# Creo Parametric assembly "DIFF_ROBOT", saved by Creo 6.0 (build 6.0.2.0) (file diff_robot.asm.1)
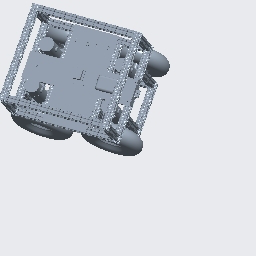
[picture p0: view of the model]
Units: Inch lbm Second (Pro/E Default); INCH, POUND, SECS

Created from: INLBS_ASM_DESIGN.ASM

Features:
  1. datum plane "ASM_RIGHT"
  2. datum plane "ASM_TOP"
  3. datum plane "ASM_FRONT"
  4. coordinate system
  5. component "FRAME_22IN_", "FRAME_22IN.ASM"
  6. component "MOTOR_MOUNT_22IN_", "MOTOR_MOUNT_22IN.PRT"
  7. component "MOTOR_MOUNT_22IN_", "MOTOR_MOUNT_22IN.PRT"
  8. component "MOTOR_", "MOTOR.PRT"
  9. component "MOTOR_", "MOTOR.PRT"
  10. component "MOTOR_MIRROR_", "MOTOR_MIRROR.PRT"
  11. component "MOTOR_MIRROR_", "MOTOR_MIRROR.PRT"
  12. component "WHEEL_AND_HUB_", "WHEEL_AND_HUB.ASM"
  13. component "WHEEL_AND_HUB_", "WHEEL_AND_HUB.ASM"
  14. component "WHEEL_AND_HUB_", "WHEEL_AND_HUB.ASM"
  15. component "WHEEL_AND_HUB.ASM"
  16. component "BATTERY_BASE.PRT"
  17. component "BATTERY.PRT"
  18. component "BATTERY.PRT"
  19. component "BATTERY.PRT"
  20. component "BATTERY.PRT"
  21. component "ROBOT_BASE_COMPONENTS.ASM"

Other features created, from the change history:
  component "ROBOT_BASE.PRT"
  component "ESP8266.PRT" (2 times)
  component "JETSON_NANO.PRT"
  component "POWER_24V_5V.PRT"
  component "FUSE_BOX.PRT"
